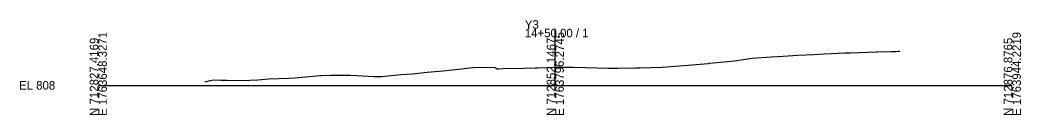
# Model space of a CAD drawing. Extents: x -26 to 2903, y -10 to 5022.
# Drawn here: x -25.7 to 302.8, y 4490.3 to 4521.4 of the extents above; entities that cross this region are included whole.
import ezdxf

# ---------------------------------------------------------------- set-up
doc = ezdxf.new("R2010")
doc.units = 0
for name, color, linetype in [('Default', 7, 'Continuous'), ('Exist Cross Section Cell', 7, 'Continuous'), ('Exist XS Ground Line', 7, 'Continuous')]:
    doc.layers.add(name, color=color, linetype=linetype)

msp = doc.modelspace()

# ---------------------------------------------------------------- linework, layer by layer
at = {"layer": 'Exist Cross Section Cell'}
for p, q in [((150, 4500), (150, 4518.54)), ((0, 4500), (150, 4500)), ((150, 4500), (300, 4500))]:
    msp.add_line(p, q, dxfattribs=at)
at = {"layer": 'Exist XS Ground Line'}
msp.add_lwpolyline([(34.95, 4501.18), (35.5, 4501.22), (36.32, 4501.51), (37.65, 4501.78), (40.2, 4501.7), (42.25, 4501.68), (47.13, 4501.62), (52.39, 4501.81), (55.82, 4502.14), (62.53, 4502.32), (64.5, 4502.43), (72.67, 4503.26), (73.19, 4503.24), (76.32, 4503.3), (81.88, 4503.35), (82.81, 4503.38), (90.56, 4502.86), (92.94, 4502.92), (99.25, 4503.55), (103.08, 4503.74), (107.94, 4504.3), (113.22, 4504.7), (118.23, 4505.29), (122.88, 4505.84), (125.38, 4505.95), (130.18, 4505.85), (130.41, 4505.71), (130.92, 4505.4), (131.5, 4505.43), (132.76, 4505.52), (139.55, 4505.65), (143.43, 4505.73), (144.3, 4505.75), (150, 4505.96), (150.05, 4505.96), (154.3, 4505.93), (155.7, 4505.91), (159.88, 4505.84), (167.48, 4505.68), (170.52, 4505.61), (176.46, 4505.74), (177.69, 4505.74), (184.96, 4505.9), (185, 4505.91), (185.05, 4505.91), (193.56, 4506.58), (193.58, 4506.58), (200.15, 4507.18), (200.25, 4507.19), (200.6, 4507.23), (208.84, 4508.05), (214.61, 4508.91), (220.87, 4509.32), (224.75, 4509.6), (229.55, 4509.85), (234.89, 4510.15), (238.24, 4510.29), (245.03, 4510.62), (246.93, 4510.69), (255.16, 4510.98), (255.61, 4511), (260.08, 4511.1), (261.73, 4511.14), (262.59, 4511.18), (263.11, 4511.24)], dxfattribs=at)

# ---------------------------------------------------------------- texts
at = {"layer": 'Default'}
msp.add_text('-', height=0.0001, dxfattribs=at).set_placement((0, 4500))
at = {"layer": 'Exist Cross Section Cell'}
for s, p in [('Y3', (140, 4518.54)), ('14+50.00 / 1', (140, 4515.74)), ('EL 808', (-26, 4498.6))]:
    msp.add_text(s, height=2.8, dxfattribs=at).set_placement(p)
for s, p in [('E 1763796.2745', (152.8, 4490)), ('N 712827.4169', (0, 4490)), ('E 1763648.3271', (2.8, 4490)), ('N 712852.1467', (150, 4490)), ('N 712876.8765', (300, 4490)), ('E 1763944.2219', (302.8, 4490))]:
    msp.add_text(s, height=2.8, rotation=90, dxfattribs=at).set_placement(p)

doc.saveas('drawing.dxf')
